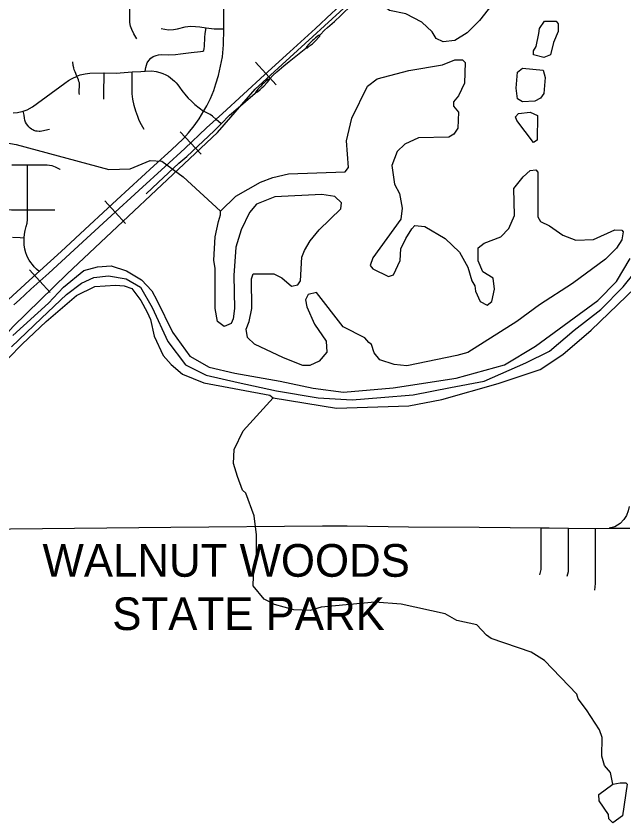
# Model space of a CAD drawing. Extents: x -1403959 to 81668, y -1400582 to 11018.
# Drawn here: x 6554.2 to 6697.8, y 7841.4 to 8032.1 of the extents above; entities that cross this region are included whole.
import ezdxf

# ---------------------------------------------------------------- set-up
doc = ezdxf.new("R2010")
doc.units = 0
for name, color, linetype in [('tdCiSectNmbr', 7, 'Continuous'), ('tdCiSectTwpRng', 7, 'Continuous'), ('tdCoPlotFrame', 7, 'Continuous'), ('tdCoSecRteBand', 7, 'Continuous'), ('tdCoSurfBitum', 7, 'Continuous'), ('tdCoTwpNameTxt', 7, 'Continuous')]:
    doc.layers.add(name, color=color, linetype=linetype)

msp = doc.modelspace()

# ---------------------------------------------------------------- linework, layer by layer
at = {"layer": 'tdCiSectNmbr'}
msp.add_lwpolyline([(6547.46, 7960.59), (6557.3, 7969.61), (6564.83, 7976.47), (6571.56, 7982.7), (6577.96, 7988.64), (6586.74, 7996.74), (6590.91, 8000.48), (6593.65, 8003.08), (6594.95, 8004.51), (6596.3, 8006.19), (6597.42, 8007.83), (6598.56, 8009.73), (6599.24, 8010.91), (6600.09, 8012.63), (6600.88, 8014.49), (6601.39, 8016.07), (6602.02, 8018.04), (6602.51, 8020.25), (6602.94, 8022.45), (6603.22, 8025.36), (6603.3, 8029.08), (6603.25, 8035.15)], dxfattribs=at)
at = {"layer": 'tdCiSectTwpRng'}
for points in [[(6626.07, 8027.7), (6627.09, 8028.75), (6627.8, 8029.4), (6629.41, 8030.87), (6630.9, 8032.27), (6631.68, 8033.03), (6632.76, 8034), (6634.34, 8035.48), (6635.65, 8036.68)], [(6582.75, 8026.73), (6582.05, 8027.95), (6581.55, 8028.91), (6581.21, 8029.7), (6581.06, 8030.62), (6581.06, 8035.23)], [(6584.82, 8019.97), (6585.19, 8021.1), (6585.56, 8021.64), (6586.06, 8022.15), (6586.6, 8022.54), (6587.25, 8022.81), (6587.86, 8022.96), (6588.5, 8023.01), (6590.12, 8022.99), (6591.83, 8023.05), (6593.06, 8023.18), (6595.59, 8023.52), (6597.8, 8023.73), (6598.29, 8023.8), (6598.53, 8023.98), (6598.65, 8024.4), (6598.73, 8025.01), (6598.77, 8027.02), (6598.84, 8028.03), (6599.07, 8029.32)], [(6588.48, 8029.19), (6590.21, 8028.9), (6591.36, 8028.92), (6592.35, 8029.12), (6594.11, 8029.55), (6595.43, 8029.7), (6596.62, 8029.67), (6597.62, 8029.56), (6599.07, 8029.32), (6600.96, 8029.11), (6603.3, 8029.08)], [(6626.07, 8027.7), (6625.64, 8027.55), (6624.97, 8026.95), (6624.53, 8026.59), (6624.2, 8026.33), (6623.9, 8026.02), (6623.37, 8025.44), (6622.82, 8024.85), (6622.69, 8024.54)], [(6622.71, 8024.54), (6623.05, 8024.61), (6623.75, 8025.22), (6624.19, 8025.58), (6624.62, 8025.94), (6625.03, 8026.38), (6625.67, 8027.03), (6625.97, 8027.38), (6626.07, 8027.7)], [(6614.12, 8017.29), (6614.86, 8018.04), (6615.81, 8018.94), (6617.48, 8020.32), (6618.75, 8021.36), (6620.67, 8022.95), (6622.69, 8024.54)], [(6622.69, 8024.54), (6622.71, 8024.54)], [(6569.14, 8013.54), (6569.1, 8013.97), (6569.09, 8014.4), (6569.11, 8014.82), (6569.16, 8015.25), (6569.19, 8015.61), (6569.19, 8015.97), (6569.14, 8016.33), (6569.05, 8016.68), (6568.92, 8017.02), (6568.57, 8017.88), (6568.12, 8018.96), (6567.95, 8019.43), (6567.81, 8019.92), (6567.71, 8020.41), (6567.63, 8021.29)], [(6553.49, 8009.26), (6554.51, 8009.36), (6555.51, 8009.55), (6555.83, 8009.66), (6556.79, 8009.99), (6558.03, 8010.64), (6565.72, 8016.27), (6566.59, 8016.85), (6567.27, 8017.3), (6567.9, 8017.62), (6568.51, 8017.86), (6568.57, 8017.88), (6569.34, 8018.19), (6570.5, 8018.49), (6571.65, 8018.65), (6574.92, 8018.7), (6574.99, 8018.7), (6577.81, 8018.64)], [(6574.92, 8012.46), (6574.92, 8013.61), (6574.99, 8018.7)], [(6577.81, 8018.64), (6581.58, 8018.9), (6583.7, 8019.05), (6584.69, 8019.11), (6586.23, 8019.17), (6587.26, 8019.04), (6588.13, 8018.82), (6588.85, 8018.57), (6589.57, 8018.23), (6590.19, 8017.88), (6590.69, 8017.53), (6591.16, 8017.16), (6591.6, 8016.74), (6592.01, 8016.3), (6592.38, 8015.83), (6592.78, 8015.29), (6593.35, 8014.52), (6594.38, 8013.24), (6594.84, 8012.75), (6595.62, 8011.97), (6596.45, 8011.2), (6598.49, 8009.61)], [(6584.46, 8005.27), (6583.85, 8006.38), (6583.31, 8007.41), (6582.96, 8008.38), (6582.46, 8009.67), (6582.11, 8010.95), (6581.76, 8012.44), (6581.61, 8013.72), (6581.58, 8018.9)], [(6584.69, 8019.11), (6584.82, 8019.97)], [(6610.67, 8013.93), (6611.2, 8014.22), (6611.83, 8014.75), (6612.34, 8015.2), (6612.74, 8015.58), (6613.48, 8016.38), (6613.98, 8016.96), (6614.12, 8017.29)], [(6614.12, 8017.29), (6613.7, 8017.14), (6613.21, 8016.7), (6612.69, 8016.26), (6612.34, 8015.96), (6611.99, 8015.56), (6611.36, 8014.9), (6610.96, 8014.43), (6610.67, 8013.93)], [(6602.65, 8006.68), (6604.58, 8008.67), (6606.13, 8009.97), (6610.67, 8013.93)], [(6562.05, 8005.29), (6560.31, 8004.91), (6559.9, 8004.84), (6559.62, 8004.84), (6559.21, 8004.88), (6558.89, 8004.93), (6558.42, 8005.09), (6558.14, 8005.21), (6557.85, 8005.37), (6557.52, 8005.61), (6557.19, 8005.92), (6556.94, 8006.23), (6556.66, 8006.65), (6556.45, 8007.04), (6556.28, 8007.5), (6556.17, 8008), (6556.08, 8008.71), (6555.83, 8009.66)], [(6602.65, 8006.68), (6601.48, 8007.7), (6600.63, 8008.43), (6600.07, 8008.83), (6598.49, 8009.61)], [(6584.91, 7990.12), (6587.77, 7992.75), (6592.66, 7997.33), (6594.51, 7998.96), (6600.98, 8004.97), (6602.65, 8006.68)], [(6553.21, 7996.97), (6556.91, 7996.94), (6560.47, 7996.95), (6561.01, 7996.96), (6561.54, 7996.93), (6562.07, 7996.89), (6562.61, 7996.76), (6563.4, 7996.5), (6564.56, 7995.92)], [(6559.64, 7971.73), (6558.99, 7972.27), (6558.45, 7972.86), (6558.04, 7973.36), (6557.66, 7973.88), (6557.31, 7974.42), (6556.99, 7974.97), (6556.7, 7975.55), (6556.5, 7976.15), (6556.27, 7977.04), (6556.11, 7978.02), (6556.06, 7978.65), (6556.07, 7979.71), (6556.16, 7980.55), (6556.34, 7981.46), (6556.61, 7982.4), (6556.81, 7983.19), (6556.87, 7983.99), (6556.87, 7986.32), (6556.91, 7996.94)], [(6564.56, 7995.92), (6564.63, 7995.88)], [(6532.08, 7986.27), (6537.73, 7986.31), (6550.41, 7986.39), (6553.14, 7986.35), (6556.87, 7986.32), (6563.38, 7986.31)], [(6553.35, 7979.82), (6555.16, 7979.77), (6556.06, 7979.71)], [(6699.03, 7916.2), (6698.83, 7915.11), (6698.4, 7914.08), (6697.8, 7913.06), (6696.91, 7912.17), (6695.67, 7911.38), (6694.31, 7911.04)], [(6530.17, 7903.58), (6532.79, 7904.77), (6535.48, 7906.15), (6537, 7906.89), (6540.49, 7908.63), (6542.85, 7909.7), (6544.22, 7910.09), (6545.81, 7910.53), (6547.23, 7910.73), (6549.58, 7910.85), (6552.88, 7910.89), (6590.73, 7911.26), (6626.62, 7911.58), (6632.42, 7911.6), (6646.88, 7911.37)], [(6646.88, 7911.37), (6663.6, 7911.26), (6678.23, 7911.1), (6680.11, 7911.1), (6684.68, 7911.05), (6691.1, 7911), (6694.31, 7911.04), (6699.23, 7911.03)], [(6677.94, 7899.98), (6678.27, 7901.24), (6678.23, 7911.1)], [(6684.37, 7899.68), (6684.74, 7900.83), (6684.68, 7911.05)], [(6690.91, 7896.38), (6691.09, 7897.97), (6691.1, 7911)]]:
    msp.add_lwpolyline(points, dxfattribs=at)
at = {"layer": 'tdCoSecRteBand'}
for p, q in [((6615.64, 8015.86), (6610.76, 8021.23)), ((6597.92, 7999.48), (6592.96, 8004.78)), ((6580.07, 7983.11), (6575.17, 7988.46)), ((6562.23, 7966.75), (6557.36, 7972.14))]:
    msp.add_line(p, q, dxfattribs=at)
for points in [[(6416.72, 7916.9), (6456.11, 7912.2), (6473.67, 7909.25), (6496.11, 7907.04), (6506.66, 7908.54), (6514.76, 7911.72), (6527.61, 7919.93), (6530.22, 7923.12), (6534.12, 7930.98), (6537.67, 7937.23), (6548.44, 7953.16), (6553.51, 7958.76), (6566.22, 7971.15), (6601.76, 8004.63), (6610.65, 8014.81), (6660.72, 8060.62), (6670.98, 8070.82)], [(6553.69, 7963.89), (6555, 7965.07), (6557.68, 7967.53), (6561.91, 7971.36), (6564.91, 7974.13), (6570.94, 7979.63), (6576.64, 7984.89), (6583.22, 7990.92), (6589.38, 7996.53), (6594.03, 8000.82), (6599.22, 8005.67), (6602.94, 8009.05), (6607.91, 8013.67), (6612.87, 8018.24), (6618.87, 8023.69), (6624.92, 8029.21), (6628.8, 8032.78), (6629.7, 8033.61), (6635.22, 8038.68), (6639.01, 8042.12), (6646.72, 8049.21), (6650.88, 8053.01), (6652.59, 8054.57)], [(6553.69, 7963.89), (6555, 7965.07), (6557.68, 7967.53), (6561.91, 7971.36), (6564.91, 7974.13), (6570.94, 7979.63), (6576.64, 7984.89), (6583.22, 7990.92), (6589.38, 7996.53), (6594.03, 8000.82), (6599.22, 8005.67), (6602.94, 8009.05), (6607.91, 8013.67), (6612.87, 8018.24), (6618.87, 8023.69), (6624.92, 8029.21), (6628.8, 8032.78), (6629.7, 8033.61), (6635.22, 8038.68), (6639.01, 8042.12), (6646.72, 8049.21), (6650.88, 8053.01), (6652.59, 8054.57)]]:
    msp.add_lwpolyline(points, dxfattribs=at)
at = {"layer": 'tdCoSurfBitum'}
for points in [[(6655.1, 8026.07), (6653.42, 8026.84), (6652.51, 8028.36), (6650.07, 8030.66), (6646.25, 8032.65), (6642.44, 8033.43), (6640, 8035.26), (6640.46, 8036.03), (6651.02, 8046.84), (6653.31, 8048.52), (6656.67, 8049.12), (6667.05, 8043.75), (6669.03, 8042.07), (6669.03, 8041), (6668.41, 8039.78), (6667.49, 8035.97), (6663.66, 8031.09), (6660.75, 8028.19), (6657.85, 8026.37), (6655.1, 8026.07)], [(6678.91, 8022.35), (6676.47, 8022.97), (6676.47, 8023.88), (6677.09, 8024.95), (6677.7, 8028), (6677.86, 8029.22), (6679.08, 8030.9), (6681.83, 8030.89), (6682.29, 8030.28), (6682.29, 8028.45), (6681.21, 8025.86), (6680.44, 8022.96), (6678.91, 8022.35)], [(6549.64, 8002.53), (6554.22, 8001.77), (6576.07, 7995.82), (6581.11, 7995.98), (6585.85, 7997.97), (6588.6, 7997.82), (6593.64, 7994.14), (6602.48, 7986.03), (6606.15, 7989.53), (6611.96, 7992.88), (6614.86, 7993.94), (6618.53, 7994.85), (6631.97, 7995.28), (6632.74, 7996.34), (6632.29, 8002.61), (6633.53, 8007.95), (6637.21, 8015.57), (6639.5, 8017.25), (6646.99, 8019.22), (6654.93, 8020.57), (6657.84, 8021.79), (6659.67, 8021.78), (6660.28, 8021.17), (6660.12, 8016.29), (6658.74, 8013.23), (6657.51, 8011.86), (6657.51, 8010.79), (6658.73, 8009.42), (6658.57, 8005.6), (6657.65, 8004.23), (6656.43, 8003.47), (6649.25, 8003.33), (6646.04, 8001.81), (6644.2, 8000.14), (6642.97, 7996.78), (6643.57, 7992.35), (6644.79, 7990.21), (6645.4, 7986.7), (6645.08, 7984.1), (6638.5, 7974.95), (6637.88, 7973.12), (6638.49, 7972.36), (6642.16, 7970.52), (6643.38, 7970.97), (6644.91, 7974.33), (6645.07, 7977.08), (6646.3, 7979.52), (6647.68, 7981.81), (6648.44, 7982.57), (6650.73, 7982.41), (6655.61, 7979.5), (6658.97, 7976.28), (6660.95, 7972.77), (6661.86, 7969.56), (6662.62, 7968.34), (6662.77, 7967.11), (6663.83, 7964.67), (6665.51, 7963.75), (6666.58, 7964.66), (6667.2, 7967.56), (6666.9, 7970.16), (6664.46, 7971.69), (6663.39, 7974.29), (6663.4, 7977.34), (6664.78, 7978.41), (6668.75, 7979.93), (6670.59, 7981.91), (6671.97, 7984.96), (6671.83, 7991.37), (6673.97, 7994.11), (6675.65, 7995.64), (6677.03, 7995.79), (6677.49, 7995.18), (6677.46, 7984.64), (6678.07, 7983.57), (6680.21, 7982.5), (6683.41, 7980.35), (6686.46, 7979.12), (6690.59, 7979.27), (6695.63, 7981.55), (6697.31, 7981.54), (6697.62, 7981.08), (6697.31, 7979.25), (6696.08, 7977.27), (6693.48, 7974.68), (6685.68, 7968.89), (6677.88, 7963.87), (6672.53, 7959.91), (6660.9, 7952.61), (6658.31, 7951.85), (6646.54, 7949.44), (6643.49, 7949.75), (6640.13, 7950.83), (6638.76, 7952.51), (6638.15, 7954.5), (6637.54, 7954.95), (6636.63, 7956.03), (6631.44, 7958.63), (6625.2, 7966.74), (6623.21, 7966.29), (6622.6, 7965.07), (6622.9, 7963.39), (6624.72, 7959.26), (6627.46, 7955.28), (6627.61, 7952.69), (6625.77, 7950.55), (6623.63, 7949.49), (6621.95, 7949.49), (6617.37, 7951.34), (6610.51, 7954.56), (6608.83, 7956.09), (6608.53, 7958.07), (6609.3, 7959.9), (6609.91, 7962.96), (6609.78, 7969.98), (6610.24, 7971.2), (6615.12, 7971.19), (6616.95, 7970.27), (6619.24, 7968.28), (6620.77, 7968.58), (6621.38, 7969.5), (6621.7, 7975.15), (6622.31, 7976.67), (6623.69, 7978.96), (6625.84, 7981.55), (6630.89, 7986.58), (6631.04, 7987.95), (6629.52, 7989.48), (6626.46, 7989.95), (6615.31, 7989.36), (6611.03, 7987.69), (6609.35, 7985.71), (6607.36, 7981.59), (6606.13, 7977.47), (6605.65, 7970.75), (6605.79, 7962.97), (6605.48, 7960.52), (6605.02, 7959.46), (6603.34, 7958.7), (6601.81, 7959.92), (6601.21, 7962.98), (6601.23, 7972.44), (6600.93, 7974.43), (6601.24, 7979.92), (6602.01, 7983.59), (6602.48, 7985.11), (6602.48, 7986.03)], [(6673.85, 8011.83), (6672.63, 8012.59), (6672.33, 8015.04), (6672.65, 8018.85), (6673.87, 8019.77), (6678.76, 8019.3), (6679.21, 8017.62), (6678.9, 8013.8), (6678.13, 8012.73), (6676.76, 8011.97), (6673.85, 8011.83)], [(6676.43, 8002.2), (6672.47, 8007.4), (6672.17, 8008.32), (6672.93, 8009.08), (6675.68, 8009.38), (6677.36, 8008.61), (6677.35, 8002.81), (6676.43, 8002.2)], [(6553.42, 7956.58), (6561.83, 7964.28), (6565.43, 7968), (6570.23, 7971.93), (6573.46, 7972.84), (6576.64, 7973.09), (6580.3, 7971.88), (6583.81, 7969.73), (6586.25, 7967.13), (6587.47, 7964.99), (6591.12, 7957.35), (6595.23, 7951.69), (6599.81, 7949.08), (6605.91, 7947.7), (6616.6, 7945.84), (6624.39, 7944.14), (6631.56, 7943.21), (6643.32, 7944.25), (6658.14, 7946.51), (6669.6, 7949.69), (6676.94, 7954.1), (6691.63, 7964.91), (6696.07, 7969.33), (6699.28, 7974.82)], [(6552.4, 7951.25), (6555.63, 7954.59), (6561.29, 7959.92), (6568.5, 7966.06), (6572.76, 7968.16), (6577.66, 7968.48), (6579.7, 7968.32), (6581.52, 7967.75), (6583.65, 7964.85), (6585.17, 7962.1), (6585.93, 7960.41), (6586.84, 7956.44), (6588.97, 7951.86), (6590.8, 7949.72), (6593.54, 7947.42), (6598.58, 7945.42), (6614.15, 7942.49), (6614.91, 7941.87), (6629.87, 7939.4), (6646.98, 7939.97), (6654.77, 7941.48), (6668.07, 7945.27), (6678, 7948.6), (6683.35, 7952.1), (6690.09, 7957.89), (6702.63, 7969.93)], [(6695.22, 7850.54), (6694.61, 7853.29), (6693.24, 7854.97), (6692.63, 7857.11), (6692.64, 7861.54), (6692.03, 7863.37), (6688.99, 7868.11), (6687.01, 7870.71), (6686.71, 7871.78), (6679.08, 7879.74), (6675.88, 7881.73), (6666.42, 7884.96), (6665.35, 7885.72), (6663.07, 7888.17), (6658.33, 7889.25), (6655.59, 7890.78), (6645.21, 7893.1), (6638.95, 7893.57), (6626.27, 7892.38), (6623.67, 7891.62), (6619.85, 7891.78), (6615.27, 7893.01), (6612.83, 7894.24), (6610.24, 7897.45), (6610.4, 7902.03), (6611.02, 7904.47), (6611.03, 7909.51), (6610.43, 7913.94), (6608.45, 7919.29), (6607.69, 7920.06), (6606.47, 7923.26), (6605.56, 7926.32), (6605.72, 7929.68), (6607.87, 7934.1), (6614.91, 7941.87)], [(6695.22, 7850.54), (6696.9, 7850.84), (6698.27, 7850.84), (6698.58, 7850.53), (6697.49, 7843.05), (6695.2, 7841.38), (6694.28, 7842.29), (6694.13, 7843.36), (6692, 7846.57), (6691.85, 7848.1), (6695.22, 7850.54)]]:
    msp.add_lwpolyline(points, dxfattribs=at)
at = {"layer": 'tdCoTwpNameTxt'}
msp.add_lwpolyline([(6553.1, 7953.89), (6560.21, 7960.73), (6566.08, 7966.27), (6569.63, 7968.96), (6572.54, 7970.31), (6575.99, 7970.69), (6580.21, 7969.99), (6583.58, 7967.99), (6586.36, 7963.22), (6590.05, 7955.22), (6594.21, 7949.68), (6599.12, 7947.22), (6606.66, 7945.52), (6615.73, 7943.52), (6625.59, 7941.83), (6633.58, 7941.37), (6640.35, 7941.98), (6648.04, 7942.59), (6656.81, 7944.29), (6664.82, 7945.82), (6674.66, 7950.13), (6680.2, 7952.9), (6686.06, 7957.83), (6692.37, 7962.76), (6697.6, 7968.14), (6702.52, 7974.14)], dxfattribs=at)

# ---------------------------------------------------------------- texts
at = {"layer": 'tdCoPlotFrame'}
for s, height, p in [('WALNUT WOODS', 7.7382, (6560.43, 7899.57)), ('STATE PARK', 7.738, (6576.92, 7886.96))]:
    msp.add_text(s, height=height, rotation=359.9908, dxfattribs=at).set_placement(p)

doc.saveas('drawing.dxf')
